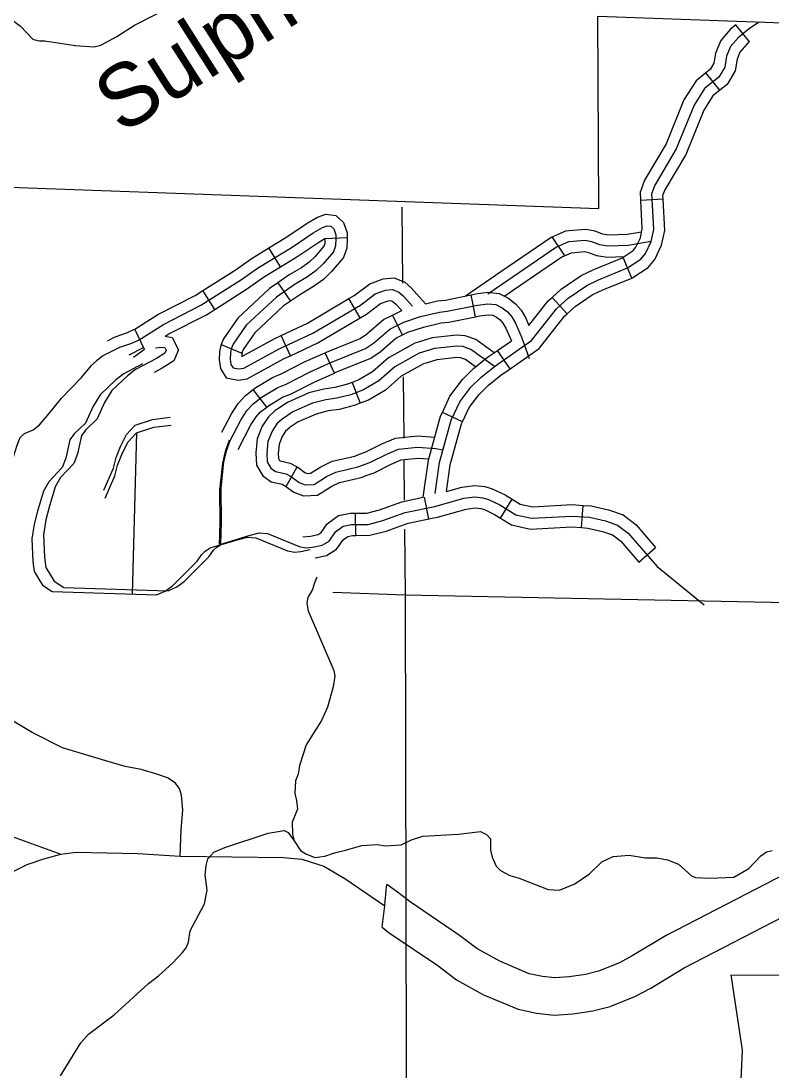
# Model space of a CAD drawing. Extents: x 1212896 to 1368412, y 378476 to 478763.
# Drawn here: x 1302391 to 1307448, y 413498 to 420570 of the extents above; entities that cross this region are included whole.
import ezdxf

# ---------------------------------------------------------------- set-up
doc = ezdxf.new("R2010")
doc.units = 0
for name, color, linetype in [('Level 10', 7, 'Continuous'), ('Level 21', 7, 'Continuous'), ('Level 31', 7, 'Continuous'), ('Level 32', 7, 'Continuous'), ('Level 35', 7, 'Continuous'), ('Level 45', 7, 'Continuous'), ('Level 5', 7, 'Continuous'), ('Level 6', 7, 'Continuous')]:
    doc.layers.add(name, color=color, linetype=linetype)

msp = doc.modelspace()

# ---------------------------------------------------------------- linework, layer by layer
at = {"layer": 'Level 10'}
for points in [[(1303462.1, 414944.5), (1303470.2, 415121.9), (1303481.8, 415254.3), (1303471.8, 415356.4), (1303458.4, 415400.4), (1303430.1, 415438.1), (1303378.2, 415473.1), (1303306.8, 415496.9), (1303199.7, 415529.8), (1303092.8, 415549.7), (1302961.8, 415586.4), (1302669.6, 415675.4), (1302466.1, 415778.5), (1302326.6, 415861.1)], [(1301781, 414223.7), (1301810.8, 414314.5), (1301895.2, 414449.7), (1301981.7, 414571.8), (1302067.6, 414657.9), (1302191.2, 414760.5), (1302251.7, 414798.2), (1302432.3, 414889.3), (1302545.6, 414927.6), (1302658.8, 414958.7), (1302761.6, 414971), (1303177.6, 414963.5), (1303462.1, 414944.5), (1304158.4, 414937), (1304283.2, 414924.3), (1304431.3, 414876.9), (1304572.8, 414794.1), (1304840.6, 414611)], [(1307608.9, 414862.8), (1306734.9, 414411.3), (1306507.3, 414273), (1306420.6, 414226.9), (1306278.7, 414171.3), (1306192.4, 414147.9), (1306081.2, 414132.3), (1305985.4, 414126.1), (1305901.7, 414134.3), (1305813.2, 414153.3), (1305614.9, 414237), (1305460.1, 414322.7), (1305343.9, 414411.2), (1305011.1, 414636.6), (1304917.8, 414709.6), (1304853.6, 414753.5)], [(1304822.2, 414467), (1304863.9, 414434.4), (1305198, 414208.1), (1305323.1, 414112.8), (1305505.4, 414011.8), (1305737.8, 413913.8), (1305863.2, 413886.9), (1305981.2, 413875.3), (1306106.7, 413883.4), (1306242.5, 413902.5), (1306357.2, 413933.5), (1306525.2, 413999.4), (1306631, 414055.6), (1306857.3, 414193.1), (1307725.7, 414641.8)]]:
    msp.add_lwpolyline(points, dxfattribs=at)
msp.add_arc((1300905.7, 415041), 3958.3, 351.66254, 355.83564, dxfattribs=at)
at = {"layer": 'Level 21'}
for p, q in [((1307170.7, 414145.6), (1307246.8, 413638)), ((1307246.8, 413638), (1307213, 412868.3))]:
    msp.add_line(p, q, dxfattribs=at)
msp.add_lwpolyline([(1307170.7, 414145.6), (1308692, 414144.8)], dxfattribs=at)
at = {"layer": 'Level 31'}
msp.add_lwpolyline([(1301930.6, 414499.1), (1301879.3, 414539), (1301847.3, 414576), (1301835.9, 414626), (1301832.5, 414670.1), (1301843.7, 414753.4), (1301863.1, 414814.8), (1301893.6, 414869.2), (1301964.3, 414941.3), (1302032, 414987.6), (1302092.8, 415023.6), (1302154.3, 415050.1), (1302222.9, 415069.8), (1302337.8, 415075.5), (1302658.8, 414958.7)], dxfattribs=at)
at = {"layer": 'Level 32'}
for p, q in [((1306714.9, 419368.9), (1306565.1, 419361.2)), ((1304437.9, 419104.9), (1304587.7, 419112)), ((1304138.3, 418913.3), (1304060.3, 419041.4)), ((1306503.5, 418838.7), (1306446.8, 418977.5)), ((1304119.9, 418805.3), (1304205.6, 418682.2)), ((1303696.1, 418627.5), (1303615.8, 418754.2)), ((1304675.7, 418570.8), (1304599.4, 418699.9)), ((1305451.9, 418577.9), (1305422.2, 418724.9)), ((1306067.9, 418597.3), (1305966.9, 418708.2)), ((1304960.2, 418455.1), (1304893.7, 418589.6)), ((1303223.2, 418358.2), (1303156.9, 418494.8)), ((1304206, 418315.7), (1304142.3, 418451.5)), ((1303739.6, 418390.4), (1303877.8, 418332)), ((1305684.8, 418228), (1305599, 418351.1)), ((1304501.1, 418199), (1304439.9, 418335.9)), ((1304045.6, 417969.1), (1303954.8, 418088.5)), ((1305364.4, 417870.3), (1305228.2, 417933.1)), ((1305137.9, 417215.8), (1305107.5, 417362.7)), ((1305619.1, 417222.5), (1305698.5, 417349.8)), ((1306166.3, 417157.8), (1306176.4, 417307.5)), ((1304645, 417105.3), (1304643.9, 417255.3)), ((1306550.9, 416926), (1306664.1, 417024.4))]:
    msp.add_line(p, q, dxfattribs=at)
for points in [[(1305180.6, 417387.9), (1305209.4, 417596.6), (1305288.3, 417881), (1305344.9, 418003.9), (1305420.6, 418103.9), (1305489.5, 418171.9), (1305578.8, 418243.8), (1305828.4, 418417.9), (1305996.8, 418632.1), (1306075.8, 418704.1), (1306200.6, 418788.6), (1306279, 418826.5), (1306475.7, 418906.8), (1306563.9, 418965.9), (1306596.4, 419004.3), (1306634.5, 419083.9), (1306651.6, 419165.2), (1306639.1, 419409.6)], [(1306565.1, 419361.2), (1306562.1, 419420.5)], [(1306714.9, 419368.9), (1306713.4, 419399)], [(1306439.9, 418974.7), (1306512.5, 419023.4), (1306531.8, 419046.1), (1306561.6, 419108.6), (1306574.8, 419171.2), (1306565.1, 419361.2)], [(1306503, 418838.5), (1306510.2, 418841.3), (1306613.4, 418910.5), (1306658.7, 418964), (1306704.7, 419060.1), (1306725.6, 419159.4), (1306714.9, 419368.9)], [(1304060.3, 419041.4), (1304174.8, 419111.1), (1304317.1, 419207.3), (1304388.6, 419248.7), (1304443.9, 419269.1), (1304510.6, 419259.1), (1304563, 419212.7), (1304586.3, 419143.3), (1304587.7, 419112)], [(1302385.9, 417763.6), (1302414.5, 417792), (1302472.1, 417815.6), (1302515, 417851), (1302579.8, 417923), (1302663.5, 418029.1), (1302795.7, 418165.8), (1302868.6, 418252.8), (1302904.2, 418286.2), (1302940.8, 418314.7), (1303055.9, 418373), (1303137.4, 418400.9), (1303187.1, 418423.5), (1303350.6, 418526.5), (1303602.6, 418655.4), (1303876.2, 418828.7), (1303983.1, 418905), (1304216.1, 419046.8), (1304357.7, 419142.5), (1304421.2, 419179.3), (1304452, 419190.6), (1304477, 419186.9), (1304497.1, 419169.1), (1304510.5, 419129.1), (1304511.7, 419102.1), (1304509.2, 419056), (1304494.7, 419015.8), (1304426.7, 418933.9), (1304379.3, 418888.3), (1304319.8, 418846.5), (1304237.6, 418797.6), (1304111.8, 418710), (1303907.2, 418520.4), (1303820.8, 418393.3), (1303807.1, 418361.1), (1303801.4, 418334.9), (1303800.1, 418291.6), (1303805, 418255.6), (1303818.9, 418233.6), (1303855.8, 418226.4), (1303891.9, 418231.1), (1304130.3, 418361.5), (1304355.6, 418467.2), (1304676.9, 418657), (1304776.9, 418731.2), (1304846.3, 418758), (1304892.3, 418761.5), (1304934.3, 418743.9), (1304964.5, 418718.2), (1305027.1, 418649.7)], [(1304437.9, 419104.9), (1304438, 419102.4), (1304436.3, 419070.8), (1304429.8, 419052.9), (1304372.7, 418984.1), (1304332.3, 418945.2), (1304279.8, 418908.4), (1304197.7, 418859.5), (1304119.9, 418805.3)], [(1304138.3, 418913.3), (1304255.8, 418984.8), (1304396.8, 419080.1), (1304438, 419103.9)], [(1304587.7, 419112), (1304588.2, 419101.8), (1304584.9, 419040.6), (1304562, 418977.2), (1304482.7, 418881.8), (1304428, 418829.1), (1304361.4, 418782.4), (1304279, 418733.3), (1304205.6, 418682.2)], [(1303615.8, 418754.2), (1303833.5, 418892.1), (1303941, 418968.8), (1304060.3, 419041.4)], [(1305966.9, 418708.2), (1306028.4, 418764.3), (1306162.4, 418855), (1306248, 418896.4), (1306446.8, 418977.5)], [(1303696.1, 418627.5), (1303917.3, 418767.6), (1304023.7, 418843.5), (1304138.3, 418913.3)], [(1304599.4, 418699.9), (1304634.6, 418720.7), (1304739.7, 418798.7), (1304829.4, 418833.4), (1304904.8, 418839.1), (1304974.8, 418809.8), (1305017.7, 418773.2), (1305115.8, 418665.8)], [(1306067.9, 418597.3), (1306121.5, 418646.1), (1306237.5, 418724.7), (1306309, 418759.3), (1306503.5, 418838.7)], [(1304119.9, 418805.3), (1304065.5, 418767.5), (1303851.1, 418568.8), (1303755.8, 418428.6), (1303739.6, 418390.4)], [(1303156.9, 418494.8), (1303312.8, 418592.9), (1303564.7, 418721.8), (1303615.8, 418754.2)], [(1304142.3, 418451.5), (1304319.9, 418534.8), (1304599.4, 418699.9)], [(1305115.8, 418665.8), (1305196.4, 418684.4), (1305250.2, 418690.1), (1305422.2, 418724.9)], [(1305422.2, 418724.9), (1305452.9, 418731.1), (1305533, 418742.5), (1305610.2, 418734.7), (1305672.9, 418703.3), (1305720.9, 418665.3), (1305758.4, 418621.9), (1305789.6, 418569.3), (1305811.3, 418519.7)], [(1305811.3, 418519.7), (1305940.6, 418684.3), (1305966.9, 418708.2)], [(1303362.4, 418446.9), (1303387.1, 418462.4), (1303639.2, 418591.5), (1303696.1, 418627.5)], [(1304205.6, 418682.2), (1304159.8, 418650.4), (1303965.5, 418470.3), (1303888.2, 418356.5), (1303877.8, 418332)], [(1304675.7, 418570.8), (1304717.7, 418595.6), (1304812.7, 418666.1), (1304862.7, 418685.5), (1304880.2, 418686.8), (1304895.3, 418680.4), (1304913.3, 418665.2), (1304954.8, 418619.7)], [(1305081.6, 418579.5), (1305209, 418609), (1305261.8, 418614.5), (1305465.9, 418655.8), (1305534.6, 418665.6), (1305588.5, 418660.1), (1305631.6, 418638.6), (1305667.8, 418609.9), (1305696.1, 418577.1), (1305721.5, 418534.3), (1305764.4, 418436.6), (1305812.7, 418295.8)], [(1303736.2, 417047.6), (1303740.3, 417197.3), (1303738, 417420.8), (1303757.9, 417601.3), (1303776.2, 417678.7), (1303798.5, 417739.1), (1303874.8, 417886.2), (1303915.1, 417947.7), (1303954.5, 417992.3), (1304015.9, 418039), (1304120, 418101.2), (1304175.6, 418123.9), (1304338.4, 418206.8), (1304478.4, 418269.4), (1304711.8, 418364.1), (1304764.3, 418400.8), (1304875, 418495.1), (1304968.3, 418541.2), (1305081.6, 418579.5)], [(1304206, 418315.7), (1304390.1, 418402), (1304675.7, 418570.8)], [(1304439.9, 418335.9), (1304448.4, 418339.7), (1304675.1, 418431.7), (1304717.6, 418461.3), (1304832.7, 418559.4), (1304893.7, 418589.6)], [(1304893.7, 418589.6), (1304954.8, 418619.7)], [(1304960.2, 418455.1), (1304996.5, 418473.1), (1305101.8, 418508.6), (1305221.2, 418536.2), (1305273, 418541.7), (1305451.9, 418577.9)], [(1305451.9, 418577.9), (1305478.4, 418583.2), (1305536.1, 418591.4), (1305567.7, 418588.3), (1305591.9, 418576.1), (1305616.7, 418556.5), (1305636.1, 418534), (1305655.9, 418500.6), (1305692.8, 418416.5)], [(1305684.8, 418228), (1305879.5, 418363.8), (1306050.9, 418581.8), (1306067.9, 418597.3)], [(1302972.7, 418416.5), (1303026.1, 418443.5), (1303109.2, 418472), (1303150.8, 418490.9), (1303156.9, 418494.8)], [(1303362.4, 418446.9), (1303408.6, 418438.8), (1303452.7, 418355.8), (1303420.6, 418280.8), (1303341.5, 418231.1), (1303287.6, 418202.2)], [(1303880.2, 418337.8), (1303877.6, 418325.6), (1303877.1, 418310.1), (1304095.7, 418429.7), (1304142.3, 418451.5)], [(1304501.1, 418199), (1304507.2, 418201.7), (1304747.1, 418299), (1304809.3, 418342.4), (1304915.8, 418433.2), (1304960.2, 418455.1)], [(1305599, 418351.1), (1305692.8, 418416.5)], [(1301592.6, 417212), (1301657.9, 417266.8), (1301685.6, 417281.1), (1301709.5, 417289.4), (1301809.2, 417295.5), (1301885.8, 417313.3), (1302011.1, 417352.7), (1302138.2, 417409.2), (1302232.3, 417471.3), (1302288.6, 417522.1), (1302313.1, 417563.4), (1302332.7, 417604.7), (1302364.5, 417713.3), (1302385.9, 417763.6), (1302414.5, 417792), (1302472.1, 417815.6), (1302515, 417851), (1302579.8, 417923), (1302663.5, 418029.1), (1302795.7, 418165.8), (1302868.6, 418252.8), (1302904.2, 418286.2), (1302940.8, 418314.7), (1303048.2, 418369.1)], [(1303296.3, 418368.9), (1303336.4, 418373.9), (1303358.7, 418370), (1303368.1, 418352.2), (1303359.8, 418332.8), (1303303.1, 418297.2), (1303163.1, 418222.2), (1303107.7, 418180.5), (1303004, 418080.2), (1302953.9, 417999.5), (1302905.2, 417889.8), (1302828.1, 417816.8), (1302799.6, 417777.4), (1302771.9, 417653.8), (1302747.6, 417590.5), (1302656.9, 417495.3), (1302620.6, 417431.8), (1302580.1, 417296.1), (1302559, 417209.7), (1302542, 417110), (1302548.6, 416959.1), (1302559.3, 416890), (1302615.6, 416797.8), (1302679.4, 416755), (1303381.8, 416732.5), (1303440.4, 416758.2), (1303489.9, 416794.8), (1303655.8, 416961), (1303688.2, 417005.4), (1303710.4, 417026.5), (1303744.7, 417049.1), (1303933.6, 417107.2), (1303994.3, 417122.9), (1304051.2, 417117.5), (1304263.5, 417030.6), (1304310.5, 417021.1), (1304353.3, 417025.6), (1304420, 417040.3), (1304465.3, 417067.2), (1304508.9, 417129.5), (1304561.3, 417168.1), (1304617.1, 417178.7), (1304729.5, 417179.5), (1304827.3, 417205), (1304977.3, 417258.7), (1305178.5, 417300.4), (1305373.3, 417355.2), (1305448.1, 417364), (1305500.6, 417358.3), (1305538, 417347.9), (1305615.2, 417311.7), (1305722.6, 417244.7), (1305828.3, 417220.8), (1306101.3, 417236), (1306219.5, 417228), (1306326.5, 417203.1), (1306408.5, 417174.9), (1306479.7, 417120.3), (1306673.8, 416896.7), (1306990.6, 416638.1)], [(1303119, 418322.4), (1303216.6, 418371.9)], [(1303221.8, 418358.4), (1303147.8, 418302.8)], [(1303739.6, 418390.5), (1303736.7, 418383.5), (1303728, 418344), (1303726.4, 418287.7), (1303734.2, 418229.8), (1303773.6, 418167.5), (1303853.5, 418151.9), (1303915.1, 418159.9), (1304163.6, 418295.8), (1304206, 418315.7)], [(1305228.2, 417933.1), (1305279, 418043.4), (1305363.1, 418154.4), (1305438.5, 418228.9), (1305532.9, 418305), (1305599, 418351.1)], [(1303954.8, 418088.5), (1303973.1, 418102.4), (1304085.8, 418169.8), (1304143.8, 418193.4), (1304305.4, 418275.7), (1304439.9, 418335.9)], [(1303208.5, 418260.2), (1303084.5, 418193.8), (1303029.1, 418152.1), (1302925.4, 418051.8), (1302875.3, 417971.1), (1302826.6, 417861.4), (1302749.5, 417788.4), (1302721, 417749), (1302693.3, 417625.4), (1302669, 417562.1), (1302578.2, 417466.9), (1302542, 417403.4), (1302501.5, 417267.7), (1302480.4, 417181.3), (1302463.4, 417081.6), (1302470, 416930.7), (1302480.7, 416861.6), (1302537, 416769.4), (1302600.8, 416726.7), (1303303.2, 416704.2), (1303361.8, 416729.8), (1303411.3, 416766.4), (1303577.2, 416932.6), (1303609.6, 416977), (1303631.8, 416998.1), (1303666, 417020.7), (1303855, 417078.8), (1303915.6, 417094.5), (1303972.6, 417089.1), (1304184.9, 417002.2), (1304231.9, 416992.7), (1304274.7, 416997.2), (1304338.7, 417011.3)], [(1304045.6, 417969.1), (1304057.2, 417977.9), (1304153, 418035.2), (1304206.3, 418056.9), (1304370.1, 418140.4), (1304501.1, 418199)], [(1305364.4, 417870.3), (1305408.4, 417965.8), (1305476.1, 418055.2), (1305538.5, 418116.9), (1305623, 418184.9), (1305684.8, 418228)], [(1303744, 417799.8), (1303808.8, 417924.8), (1303854.2, 417994.2), (1303902.2, 418048.5), (1303954.8, 418088.5)], [(1303852.6, 417683.5), (1303938.5, 417849), (1303973.8, 417903), (1304004.8, 417938.1), (1304045.6, 417969.1)], [(1305100, 417362.1), (1305134.4, 417612.1), (1305216.3, 417907.4), (1305228.2, 417933.1)], [(1305256.8, 417401.8), (1305281.6, 417581.6), (1305357.6, 417855.6), (1305364.4, 417870.3)], [(1303168.6, 417795.1), (1303139.2, 416709.4)], [(1303168.6, 417795.1), (1303141.4, 416790.3)], [(1303793.9, 417747.6), (1303765.3, 417670.3), (1303747, 417592.9), (1303727, 417412.3), (1303729.3, 417188.9), (1303725.3, 417038.9)], [(1305256.8, 417401.8), (1305358.4, 417430.3), (1305447.7, 417440.9), (1305515, 417433.6), (1305564.6, 417419.8), (1305651.7, 417378.9), (1305698.5, 417349.8)], [(1304643.9, 417255.3), (1304719.4, 417255.8), (1304804.7, 417278.1), (1304956.6, 417332.5), (1305100, 417362.1)], [(1305698.5, 417349.8), (1305752, 417316.4), (1305834.7, 417297.7), (1306101.7, 417312.5), (1306176.4, 417307.5)], [(1305171, 417223.6), (1305195.9, 417228.8), (1305387.7, 417282.8), (1305448.4, 417289.9), (1305486.7, 417285.8), (1305512.3, 417278.7), (1305579.9, 417246.9), (1305619.1, 417222.5)], [(1306176.4, 417307.5), (1306230.8, 417303.8), (1306347.6, 417276.6), (1306445.2, 417243.1), (1306532.3, 417176.2), (1306664.1, 417024.4)], [(1304288.9, 417095.7), (1304341.1, 417101.1), (1304391.5, 417112.3), (1304412.1, 417124.5), (1304453.5, 417183.6), (1304530, 417239.9), (1304609.6, 417255), (1304643.9, 417255.3)], [(1304645, 417105.3), (1304739.2, 417106), (1304849, 417134.6), (1304997.3, 417187.7), (1305171, 417223.6)], [(1305619.1, 417222.5), (1305694.2, 417175.7), (1305822.1, 417146.7), (1306100.9, 417162.3), (1306166.3, 417157.8)], [(1306166.3, 417157.8), (1306208.6, 417155), (1306306.1, 417132.3), (1306373.3, 417109.2), (1306429, 417066.4), (1306550.9, 416926)], [(1304370.9, 416954.1), (1304447.5, 416971), (1304516.5, 417012), (1304562.3, 417077.4), (1304591.5, 417098.9), (1304624.3, 417105.1), (1304645, 417105.3)]]:
    msp.add_lwpolyline(points, dxfattribs=at)
at = {"layer": 'Level 35'}
for points in [[(1302308.6, 420594), (1302387, 420534.7), (1302470.7, 420446.8), (1302484.7, 420441.9), (1302516.9, 420436.3), (1302551.9, 420437), (1302756.3, 420405.5), (1302883, 420395), (1302927.9, 420407.3), (1303037, 420465.5), (1303155.9, 420542), (1303429.8, 420681.2)], [(1304383.5, 416823.9), (1304364.9, 416779.9), (1304354.4, 416740.7), (1304323, 416686.2), (1304315.4, 416649.1), (1304325.9, 416597.1), (1304496.6, 416195.1), (1304505, 416157.1), (1304493.7, 416084.9), (1304455.2, 415949.2), (1304414.3, 415858.6), (1304311.2, 415695.1), (1304265.7, 415555.3), (1304258.3, 415498.5), (1304238.9, 415451.9), (1304235.8, 415367.6), (1304247.2, 415319.7), (1304253.8, 415260.6), (1304217.8, 415173.1), (1304219.6, 415093.9), (1304230, 415047.9), (1304272.6, 414983.3), (1304308.7, 414960.6), (1304368.8, 414936.2), (1304436.6, 414946), (1304501.2, 414968.7), (1304576.8, 414984.5), (1304685.2, 415016.8), (1304791.9, 415022.9), (1304842.8, 415014.5), (1304951.5, 415021.6), (1305021, 415054.5), (1305097.5, 415079.3), (1305337.7, 415093.9), (1305485.2, 415110.6), (1305526.3, 415090), (1305551.5, 415061.2), (1305553.3, 414986), (1305562.8, 414938), (1305591.3, 414877.2), (1305620.5, 414848.5), (1305682.7, 414815.1), (1305745.7, 414796.7), (1305940, 414720.7), (1306018.1, 414717), (1306121.2, 414758.7), (1306220.2, 414825.9), (1306301.2, 414906.9), (1306377.6, 414942.8), (1306486.2, 414953), (1306595.2, 414934.1), (1306673, 414933), (1306744.9, 414920.7), (1306818, 414890.4), (1306905.6, 414813.2), (1306932.7, 414802.5), (1307029.5, 414796.5), (1307192, 414804.3), (1307292.1, 414862.5), (1307373, 414947.5), (1307410.7, 414974), (1307449.1, 414983.5)], [(1302657.3, 413465.9), (1302793.7, 413688.8), (1302844.9, 413746.5), (1303018.2, 413876.6), (1303250.4, 414088.5), (1303316.7, 414140.3), (1303414.6, 414226.5), (1303479.7, 414296.4), (1303503.3, 414328.7), (1303519.9, 414365.5), (1303530.1, 414441.2), (1303625.9, 414624.6), (1303644.9, 414716), (1303632, 414816.1), (1303637.3, 414883.2), (1303649.8, 414926.5), (1303690.2, 414972), (1303763.7, 415003.8), (1304055, 415099.2), (1304162.5, 415117.4), (1304190.6, 415104.6), (1304230, 415047.9)]]:
    msp.add_lwpolyline(points, dxfattribs=at)
at = {"layer": 'Level 45'}
for p, q in [((1307299, 420426.4), (1307204.4, 420542.8)), ((1307095.9, 420102.7), (1307002.6, 420220.2)), ((1305964.4, 419116.4), (1306049.1, 418992.6)), ((1304621.5, 418135.6), (1304675.5, 417995.6)), ((1304176.8, 417435.5), (1304249.7, 417566.6))]:
    msp.add_line(p, q, dxfattribs=at)
for points in [[(1307360.5, 420562.6), (1307296.1, 420518.9), (1307219.9, 420456.9), (1307168.6, 420398.2), (1307141.4, 420331.8), (1307129.2, 420259.5), (1307090, 420192), (1306994, 420115.8), (1306923.2, 420003.8), (1306803.7, 419707.9), (1306658.3, 419464.9), (1306639.1, 419409.6)], [(1307204.4, 420542.8), (1307166.7, 420512.1), (1307102.8, 420439), (1307067.5, 420352.9), (1307056.2, 420285.9), (1307031.1, 420242.8), (1307002.6, 420220.2)], [(1307295.2, 420431.2), (1307232.1, 420359), (1307212.6, 420311.5), (1307199.5, 420234.1), (1307146.6, 420143), (1307095.9, 420102.7)], [(1307002.6, 420220.2), (1306936.3, 420167.6), (1306855, 420038.8), (1306735.1, 419742.1)], [(1307095.9, 420102.7), (1307049.5, 420065.9), (1306989, 419970.1), (1306869.8, 419675.1), (1306864.4, 419666.1)], [(1306735.7, 419743.1), (1306588.7, 419497.4), (1306562.1, 419420.5)], [(1306864.4, 419666.1), (1306725.4, 419433.7), (1306713.4, 419399)], [(1306107.7, 419158.6), (1306058.5, 419154.1), (1305960.7, 419111.7), (1305622.6, 418880.2)], [(1306569.9, 419147.9), (1306471.9, 419132), (1306347, 419127.5), (1306307.7, 419133.6), (1306256.4, 419153.4), (1306193.8, 419166.4), (1306107.7, 419158.6)], [(1306634.5, 419083.9), (1306479.2, 419058.6), (1306342.5, 419053.7), (1306288.6, 419062.1), (1306235.5, 419082.6), (1306189.5, 419092.1), (1306076.9, 419081.9), (1305996.5, 419046.9), (1305533.9, 418730.3)], [(1306121.3, 419009.2), (1306096.1, 419006.9), (1306033.6, 418979.8), (1305707.3, 418756.5)], [(1306449.3, 418981.1), (1306338, 418977.1), (1306268.7, 418987.9), (1306213.9, 419009.1), (1306185.2, 419015), (1306121.3, 419009.2)], [(1305622.6, 418880.2), (1305384.5, 418717.3)], [(1305707.3, 418756.5), (1305647.9, 418715.8)], [(1305073.6, 418409.2), (1305043.3, 418399.7), (1304864.8, 418302.2), (1304757.3, 418206.1), (1304665.7, 418152.6), (1304621.5, 418135.6)], [(1305577, 418335.7), (1305453.5, 418424.3), (1305382.7, 418449.4), (1305324.1, 418454.4), (1305159.4, 418436.1), (1305073.6, 418409.2)], [(1305578.8, 418243.8), (1305419, 418358.4), (1305367, 418376.8), (1305325.1, 418380.4), (1305174.6, 418363.7), (1305072.2, 418331.6), (1304907.5, 418241.6), (1304800.8, 418146.3), (1304697.7, 418086.1), (1304612.2, 418053.1), (1304518.7, 418029), (1304444, 418018.2), (1304353.5, 417995.2), (1304221.4, 417936.7), (1304149.1, 417888.8), (1304113.5, 417856.3), (1304081.5, 417806.6), (1304054, 417738), (1304045.7, 417659), (1304049.3, 417601.1), (1304074.4, 417557.3), (1304105.8, 417535.6), (1304175.8, 417520.3), (1304212.9, 417499.7), (1304264.2, 417462.2), (1304305.2, 417446), (1304365, 417449), (1304447.3, 417501.2), (1304512.1, 417532.3), (1304660.1, 417566.6), (1304739.6, 417595.5), (1304853.7, 417652.9), (1304932.2, 417685.8), (1305061.7, 417700.2), (1305184.5, 417690.5), (1305232.2, 417681.9)], [(1305451.1, 418241.4), (1305383.3, 418290), (1305350.7, 418301.6), (1305326, 418303.7), (1305190.4, 418288.6), (1305118.6, 418266.1)], [(1305118.6, 418266.1), (1305102.2, 418261), (1304951.9, 418178.8), (1304846, 418084.2), (1304730.9, 418017), (1304675.5, 417995.6)], [(1304621.5, 418135.6), (1304589.7, 418123.3), (1304504.2, 418101.3), (1304429.6, 418090.5), (1304329.3, 418065), (1304186, 418001.4), (1304114.3, 417954)], [(1304675.5, 417995.6), (1304635.6, 417980.2), (1304533.8, 417954), (1304459, 417943.2), (1304378.6, 417922.7), (1304258.2, 417869.4), (1304197.1, 417828.9)], [(1304114.3, 417954), (1304103.7, 417947), (1304056.8, 417904.3), (1304015.8, 417840.5), (1303981.9, 417755.8), (1303971.9, 417660.6), (1303976.9, 417579.4), (1304018.8, 417506.2), (1304076, 417466.8), (1304149.5, 417450.7), (1304176.8, 417435.5)], [(1302950, 417410.2), (1303014.3, 417559.2), (1303031.8, 417630.9), (1303060.7, 417703), (1303102.5, 417785.6), (1303160, 417848.4), (1303277.3, 417886.7), (1303394.8, 417901)], [(1302958.6, 417356.9), (1303022.9, 417505.9), (1303040.4, 417577.6), (1303069.3, 417649.7), (1303111.1, 417732.3), (1303168.6, 417795.1), (1303285.9, 417833.4), (1303403.4, 417847.7)], [(1304197.1, 417828.9), (1304196.2, 417828.3), (1304172.4, 417806.6), (1304149.7, 417771.4), (1304128.9, 417719.4), (1304122.3, 417657.4), (1304124.4, 417623.6), (1304132.1, 417610.3), (1304136.8, 417607), (1304203.1, 417592.6), (1304249.7, 417566.6)], [(1304670.5, 417651.7), (1304709.3, 417665.8), (1304821.8, 417722.3), (1304912.8, 417760.5), (1305060.5, 417776.9), (1305177.6, 417767.7)], [(1304249.6, 417566.7), (1304254.2, 417564.2), (1304301.3, 417529.6), (1304317.9, 417523.1), (1304341.1, 417524.3), (1304410.2, 417568.1), (1304486.6, 417604.8), (1304638.3, 417640), (1304670.5, 417651.7)], [(1304721.8, 417510.7), (1304768.8, 417527.8), (1304884.5, 417586), (1304950.9, 417613.8), (1305062.9, 417626.3), (1305135.6, 417620.5)], [(1304173.2, 417437.5), (1304228.4, 417397.1), (1304293.1, 417371.7), (1304388.1, 417376.4), (1304483.1, 417436.7), (1304536.6, 417462.4), (1304681.1, 417495.9), (1304721.8, 417510.7)]]:
    msp.add_lwpolyline(points, dxfattribs=at)
at = {"layer": 'Level 5'}
for points in [[(1304955.3, 419316.2), (1304959.6, 418804.3)], [(1304964.9, 418174.2), (1304968.3, 417760.1)], [(1304969.6, 417613.1), (1304971.8, 417342.5)], [(1304973.5, 417146.7), (1304977.2, 416702.3), (1304989.9, 411461.9), (1304999.6, 410244.2)], [(1310237.8, 416596.6), (1304977.2, 416702.3), (1304490.3, 416719.9)]]:
    msp.add_lwpolyline(points, dxfattribs=at)
at = {"layer": 'Level 6'}
msp.add_lwpolyline([(1298282, 416932.8), (1298296.1, 418277.7), (1300953.3, 418184), (1300954.1, 417707.1), (1301264.5, 417691.4), (1301267.6, 418169.4), (1302325.3, 418129.7), (1302316.8, 419451.2), (1306281.1, 419306.5), (1306275.8, 420601.1), (1308897.1, 420508), (1308880.3, 421852.2)], dxfattribs=at)

# ---------------------------------------------------------------- texts
at = {"layer": 'Level 35'}
msp.add_text('Sulphur', height=422.4, rotation=32.48524, dxfattribs=at).set_placement((1303067.2, 419800.4))

doc.saveas('drawing.dxf')
